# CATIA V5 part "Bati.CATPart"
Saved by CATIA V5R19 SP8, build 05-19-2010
Part number: Bati
Bounding box of the stored display mesh (mm): x -25 to 34, y -65 to 65, z -5 to 54.83
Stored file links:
  F:\Projet3\Bati.CATPart
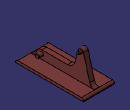
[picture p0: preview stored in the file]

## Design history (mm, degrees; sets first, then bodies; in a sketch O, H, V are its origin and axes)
Parameters
  Longueur = 10 mm
Body1 (main body)
  Sketch1 on yz-plane, origin (0, 0, 0), H (0, 1, 0), V (0, 0, 1)
    point P1 (60, 0)
    line L1 (60, 0) -> (-60, 0)
    point P2 (-60, 0)
    line L2 (-50.9535, 5.7384) -> (-48.8227, 10.2616)
    line L3 (-39.7763, 16) -> (9.2034, 16)
    line L4 (23.6923, 27.1177) -> (30.1704, 51.2941)
    line L5 (39.8296, 51.2941) -> (51.6095, 7.331)
    arc A1 centre (-39.7763, 6) radius 10 from (-48.8227, 10.2616) to (-39.7763, 16) cw
    arc A2 centre (9.2034, 31) radius 15 from (9.2034, 16) to (23.6923, 27.1177) ccw
    arc A3 centre (35, 50) radius 5 from (39.8296, 51.2941) to (30.1704, 51.2941) ccw
    point P11 (35, 50)
    arc A4 centre (61.2688, 9.9192) radius 10 from (60, 0) to (51.6095, 7.331) cw
    point P12 (60, 0)
    arc A5 centre (-60, 10) radius 10 from (-50.9535, 5.7384) to (-60, 0) cw
    point P16 (-60, 0)
    radius A1 = 10 {= Longueur *1}
    radius A2 = 15 {= Longueur *1.5}
    radius A4 = 10 {= Longueur *1}
    radius A5 = 10 {= Longueur *1}
    length L2 = 5 {= Longueur *0.5}
    radius A3 = 5 {= Longueur *0.5}
    distance P1 V = 60 {= Longueur *6}
    distance P2 V = 60 {= Longueur *6}
    angle L4 L1 = 75
    angle L5 L1 = 75
    distance P11 L1 = 50 {= Longueur *5}
    distance L3 L1 = 16 {= Longueur *1.6}
    distance P11 V = 35 {= Longueur *3.5}
    coincidence: P1 H, P12 P1, P16 P2
    horizontal: L1 H, L3 H
    tangency: A1 L2, A1 L3, A2 L3, A2 L4, A4 L5, A5 L2, A5 L1, L4 A3, L5 A3
  Pad1: profile Sketch1, direction (1, 0, 0), length 9 {= Longueur *0.9}
  Sketch2 on end face of Pad1, origin (9, 0, 0), H (0, 1, 0), V (0, 0, 1)
    circle A1 centre (35, 50) radius 2
    reference projected arc E1 centre (35, 50) radius 5 from (39.8296, 51.2941) to (30.1704, 51.2941) ccw from edge [face of Pad1 from Sketch1.A3 | end face of Pad1]
    radius A1 = 2 {= Longueur *0.2}
    concentricity: A1 E1
  Pad2: profile Sketch2, direction (1, 0, 0), length 7 {= Longueur *0.7}
  Sketch3 on face of Pad1 from Sketch1.L1, origin (0, 0, 0), H (1, 0, 0), V (0, -1, 0)
    line L1 (-25, 65) -> (34, 65)
    line L2 (34, 65) -> (34, -65)
    line L3 (34, -65) -> (-25, -65)
    line L4 (-25, -65) -> (-25, 65)
    reference projected line E1 (0, 60) -> (0, -60) from edge [start face of Pad1 | face of Pad1 from Sketch1.L1]
    reference projected line E2 (0, 60) -> (0, -60) from edge [start face of Pad1 | face of Pad1 from Sketch1.L1]
    distance L2 E1 = 34 {= Longueur *3.4}
    distance E2 L4 = 25 {= Longueur *2.5}
    distance L1 H = 65 {= Longueur *6.5}
    distance L3 H = 65 {= Longueur *6.5}
    horizontal: L1 H, L3 H
    vertical: L2 V, L4 V
  Pad3: profile Sketch3, direction (0, 0, -1), length 5 {= Longueur *0.5}
  Fillet1: radius 4 {= Longueur *0.4}, on edge [start face of Pad3 | face of Pad3 from Sketch3.L1]
  Fillet2: radius 4 {= Longueur *0.4}, on edge [start face of Pad3 | face of Pad3 from Sketch3.L3]
  Chamfer1: length 1 {= Longueur *0.1}, angle 45, on edge [face of Pad2 from Sketch2.A1 | end face of Pad2]
  Sketch4 on end face of Pad1, origin (9, 0, 0), H (0, 1, 0), V (0, 0, 1)
    circle A1 centre (-40, 9) radius 4
    point P1 (-40, 9)
    radius A1 = 4 {= Longueur *0.4}
    distance P1 V = 40 {= Longueur *4}
    distance P1 H = 9 {= Longueur *0.9}
  Pad4: profile Sketch4, direction (1, 0, 0), length 9 {= Longueur *0.9}
  Chamfer2: length 1 {= Longueur *0.1}, angle 45, on edge [face of Pad4 from Sketch4.A1 | end face of Pad4]
  Sketch5 on end face of Pad1, origin (9, 0, 0), H (0, 1, 0), V (0, 0, 1)
    circle A1 centre (35, 50) radius 3
    reference projected circle E1 centre (35, 50) radius 2 from edge [face of Pad2 from Sketch2.A1 | face of Chamfer1]
    radius A1 = 3 {= Longueur *0.3}
    concentricity: A1 E1
  Pad5: profile Sketch5, direction (1, 0, 0), length 3.5 {= Longueur *0.35}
